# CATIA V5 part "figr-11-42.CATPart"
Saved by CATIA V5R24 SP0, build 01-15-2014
Part number: Part1
Bounding box of the stored display mesh (mm): x -82.6 to 82.6, y -78 to 78, z 0 to 136
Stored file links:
  D:\KAVITA\CATIA V5-6R2014 Project_ Kavita\CATIA V5-6R2014_partfiles\Partfiles\c11_catia_v5-6r2014_prt\figr-11-42.CATPart
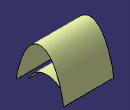
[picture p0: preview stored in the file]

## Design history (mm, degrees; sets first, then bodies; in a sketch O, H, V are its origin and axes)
Set1
  Extrude1: Element1 Sketch1, Lim1 59, Lim2 59, Direction yz-plane
  Affinity1: ToTransfor Extrude1, RatioX 1.4, RatioY 1.3, RatioZ 3.4
Body1 (main body)
  Sketch1 on yz-plane, origin (0, 0, 0), H (0, 1, 0), V (0, 0, 1)
    arc A1 centre (0, -25) radius 65 from (-60, 0) to (60, 0) cw
    point P2 (-60, 0)
    point P3 (60, 0)
    coincidence: P2 H, P3 H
